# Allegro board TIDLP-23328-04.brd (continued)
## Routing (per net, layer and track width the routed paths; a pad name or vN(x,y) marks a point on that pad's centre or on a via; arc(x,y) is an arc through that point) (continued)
TIVA_EXP_I2C_SCL: length 24.6
  TOP w0.099: J5.37 38,42 v1(37.68,41.67) ; v2(42.89,27.76) 43.42,27.76 44.83,29.17 46.22,29.17 R25.1
  LY4-SIG w0.102: v2(42.89,27.76) 42.57,27.76 42.18,28.16 42.18,28.52 43.13,29.48 43.13,30 42.81,30.32 42.81,31.16 42.18,31.79 42.18,33.87 40.91,35.14 40.52,35.14 39.45,36.21 39.45,38.89 38.22,40.12 38.22,40.65 37.68,41.2 v1(37.68,41.67)
  BOTTOM w0.099: U1.D2 v2(42.89,27.76)
TIVA_EXP_I2C_SDA: length 24.4
  TOP w0.099: v2(44.73,28.35) 44.82,28.26 45.88,28.26 R26.1 ; v1(38.65,42.18) 38.4,42.43 J5.35
  LY3-SIG w0.102: v2(44.73,28.35) 44.73,29.08 45.16,29.51 45.16,33.73 44.45,34.44 44.45,35.14 44.94,35.63 44.94,36.89 44.26,37.57 43.33,37.57 41.61,39.29 38.72,39.29 38.11,39.9 38.11,41.64 v1(38.65,42.18)
  BOTTOM w0.099: U1.D1 v2(44.73,28.35)
TIVA_FLASH_CLK: length 38.8
  TOP w0.099: v1(40.64,38.04) 40.4,38.28 J5.26
  LY4-SIG w0.102: v1(27.05,35.28) 27.05,30.66 26.74,30.34 26.74,28.13 29.72,25.15 29.72,22.61 30.23,22.1 34.03,22.1 34.27,21.86 37.05,21.86 v2(37.14,21.77)
  LY7-SIG w0.102: v1(27.05,35.28) 27.82,36.05 29.07,36.05 31.09,38.07 39.22,38.07 39.65,37.64 40.24,37.64 v1(40.64,38.04)
  BOTTOM w0.099: U1.U14 v2(37.14,21.77)
TIVA_FLASH_CSZ: length 60.9
  TOP w0.099: J5.24 40.8,38.45 41.28,37.97 41.28,37.6 R17.1 42.17,37.35 v1(42.3,37.22)
  LY7-SIG w0.102: v2(38.38,18.99) 38.38,17.92 38.32,17.87 38.32,17.55 38.38,17.5 38.38,14.81 39.2,13.99 39.91,13.99 40.6,13.31 50.94,13.31 54.71,17.07 54.71,18.46 55.44,19.19 55.44,35.11 54.74,35.81 53.98,35.81 52.24,37.56 49.69,37.56 49.15,38.1 48.33,38.1 47.45,37.22 v1(42.3,37.22)
  BOTTOM w0.099: U1.V12 38.92,20.49 38.92,19.53 v2(38.38,18.99)
TIVA_FLASH_DO: length 36.4
  TOP w0.099: v1(28.17,28.8) 28.95,28.8 30.33,27.42 30.33,26.52 30.94,25.91 30.94,25.3 31.58,24.65 33.45,24.65 33.7,24.89 34.29,24.89 34.38,24.98 34.78,24.98 35.08,24.68 v2(36.64,24.68) ; v1(40.29,41.27) 40,41.56 J5.27
  LY8-SIG w0.102: v1(40.29,41.27) 40.13,41.11 40.13,39.31 38.83,38.02 38.02,38.02 37.62,37.61 37.62,36.71 36.62,35.71 30.07,35.71 28.69,34.34 28.69,29.32 v1(28.17,28.8)
  BOTTOM w0.099: v1(40.29,41.27) 40.29,41.26 ; v2(36.64,24.68) 36.78,24.83 37.08,24.83 U1.K15
TIVA_IIC0_SCL: length 58.3
  TOP w0.099: v1(38.66,37.02) 38.7,37.02 38.75,36.97 38.99,36.97 R35.1 39.2,37.52 J5.32
  LY7-SIG w0.102: v1(38.66,37.02) 41.05,37.02 41.91,36.16 46.9,36.16 48.64,34.42 52.7,34.42 54.29,32.83 54.29,30.5 54.58,30.21 54.58,18.98 54.31,18.71 54.31,17.33 50.73,13.74 41.21,13.74 40.51,14.44 40.51,15.24 39.37,16.38 39.37,18.76 v2(39.14,18.99)
  BOTTOM w0.099: v2(39.14,18.99) U1.V11
TIVA_IIC0_SDA: length 37.7
  TOP w0.099: v2(36.85,24.18) 36.71,24.18 36.34,23.8 35.15,23.8 34.79,23.44 34.25,23.44 34.02,23.2 33.33,23.2 32.89,23.64 30.28,23.64 29.17,24.74 29.17,26.81 28.46,27.52 v1(28.46,27.52) ; J5.30 39.6,38.01 39.88,37.73 40.01,37.73 R36.1 39.81,36.77 39.09,36.77 38.95,36.64 38.18,36.64 38.18,36.63 37.86,36.63 37.86,36.64 36.71,36.64 v1(36.59,36.76)
  LY8-SIG w0.102: v1(36.59,36.76) 29.54,36.76 26.07,33.3 26.07,29.34 27.89,27.52 v1(28.46,27.52)
  BOTTOM w0.099: v2(36.85,24.18) 36.85,23.98 U1.M16
TIVA_RESETZ: length 26.1
  TOP w0.099: U13.6 27.57,15.07 R45.2 27.51,15.86 v1(27.44,15.93)
  LY7-SIG w0.102: v2(33.82,22.56) 31.87,22.56 27.44,18.13 v1(27.44,15.93) 27.44,12.7 24.86,10.11 24.49,10.11 v1(23.14,8.76)
  BOTTOM w0.099: v2(33.82,22.56) 34.81,22.56 34.88,22.49 35.36,22.49 U1.P18 ; J4.10 v1(23.14,8.76)
TIVA_TCK: length 37.7
  TOP w0.099: v2(37.14,30.54) 36.79,30.19 34.98,30.19 34.67,29.88 33.66,29.88 33.35,30.19 v1(28.15,30.19)
  BOTTOM w0.099: U1.B15 37.14,28.87 37.16,28.89 37.16,30.52 v2(37.14,30.54) ; J4.4 26.95,8.91 26.73,9.12 26.73,10.65 25.91,11.47 25.91,14.82 24.34,16.39 24.34,25.61 25.06,26.33 25.06,27.91 27.04,29.89 27.85,29.89 v1(28.15,30.19)
TIVA_TDI: length 43.2
  TOP w0.099: v1(26.59,31.04) 27.45,31.9 32.85,31.9 34.27,30.48 34.7,30.48 35.13,30.91 37.35,30.91 37.5,30.76 37.5,29.63 38.5,28.63 38.5,28.1 v2(37.64,27.24)
  BOTTOM w0.099: U1.D14 37.64,27.24 v2(37.64,27.24) ; v1(26.59,31.04) 26.59,30.37 25.43,29.21 24.76,29.21 23.88,28.33 23.88,26.42 23.42,25.96 23.42,14.68 24.09,14.01 24.09,10.4 24.41,10.09 J4.8
TIVA_TDO: length 38.7
  TOP w0.099: v1(27.56,30.48) 27.56,30.13 27.87,29.81 32.24,29.81 32.91,29.15 33.33,29.15 33.8,29.61 34.63,29.61 34.97,29.27 37.11,29.27 v2(38.12,28.26)
  BOTTOM w0.099: v1(27.56,30.48) 27.15,30.48 27.05,30.38 27.05,30.35 24.48,27.78 24.48,26.38 23.84,25.74 23.84,15.03 24.67,14.2 24.67,12.16 25.08,11.75 25.08,9.61 25.68,9 J4.6 ; U1.C14 v2(38.12,28.26)
TIVA_TMS: length 36
  TOP w0.099: v1(28.17,29.43) 32.18,29.43 32.84,28.77 33.14,28.77 33.78,28.13 34.14,28.13 34.62,28.61 36.75,28.61 37.14,28.22 v2(37.14,27.83)
  BOTTOM w0.099: J4.2 28.22,7.86 27.7,8.38 27.7,8.76 27.08,9.37 27.08,14.5 24.92,16.67 24.92,19.96 26.09,21.14 26.09,23.55 26.8,24.26 26.8,28.06 v1(28.17,29.43) ; U1.C15 v2(37.14,27.83)
TIVA_TRIG_IN_0: length 21.6
  TOP w0.099: v1(38.62,40.39) 38.55,40.39 38,39.85 J5.38
  LY3-SIG w0.102: v1(38.62,40.39) 38.62,40 38.99,39.63 41.65,39.63 43.43,37.85 44.76,37.85 45.32,37.28 45.32,34.4 45.56,34.16 45.56,29.31 45.12,28.87 45.12,28.21 44.66,27.75 v2(44.66,26.53)
  BOTTOM w0.099: U1.G1 44.39,26.26 v2(44.66,26.53)
TIVA_TRIG_IN_1: length 22.7
  TOP w0.099: v1(36.93,37.53) 37.6,38.2 J5.40
  LY3-SIG w0.102: v2(45.25,26.53) 45.25,26.36 44.92,26.03 44.53,26.03 44.27,26.29 44.27,28.63 43.56,29.34 43.56,33.86 42.92,34.5 42.92,35.98 41.26,37.64 39.71,37.64 39.26,38.09 37.5,38.09 v1(36.93,37.53)
  BOTTOM w0.099: v2(45.25,26.53) 45.25,26.36 44.88,25.99 43.92,25.99 U1.G2
TIVA_TRIG_SEL: length 20.4
  TOP w0.099: v1(37.43,40.39) 37.2,40.16 J5.42
  LY3-SIG w0.102: v2(43.97,30.54) 44.63,30.54 44.85,30.75 44.85,33.47 43.84,34.48 43.84,35.51 44.62,36.3 44.62,36.75 44.15,37.23 43.16,37.23 41.61,38.79 38.22,38.79 37.43,39.58 v1(37.43,40.39)
  BOTTOM w0.099: U1.B2 43.31,29.1 43.31,29.51 43.39,29.58 43.39,29.69 43.46,29.76 43.46,30.16 43.83,30.54 v2(43.97,30.54)
TIVA_VSYNC_MASK: length 15.7
  LY4-SIG w0.102: v1(48.68,36.44) 48.63,36.44 48.37,36.18 48.37,36.18 48.15,35.96 48.15,35.95 48.13,35.94 48.13,34.92 48.64,34.42 48.64,34.04 47.56,32.95 47.56,30.73 47.18,30.35 46.87,30.35 46.23,29.71 46.23,27.18 45.85,26.8 v2(45.85,25.78)
  BOTTOM w0.099: v2(45.85,25.78) 45.72,25.78 45.7,25.76 U1.H2 ; v1(48.68,36.44) 48.79,36.33 U9.5
TSCL: length 17.2
  LY8-SIG w0.102: v1(38.02,37.01) 38.02,37.01 38.02,36.04 38.56,35.49 39.79,35.49 41.5,33.78 43.8,33.78 44.97,32.61 44.97,29.26 44.35,28.63 43.5,28.63 v2(43.13,28.26)
  BOTTOM w0.099: U1.C2 v2(43.13,28.26) ; v1(38.02,37.01) 38.02,37.01 37.95,37.08 J2.13
TSDA: length 21.1
  BOTTOM w0.099: U1.C1 44.14,28.32 45.38,29.56 45.38,31.58 42.88,34.09 42.88,37.92 41.81,38.99 41.31,38.99 39.49,40.81 36.48,40.81 36.23,40.56 36.23,40.06 35.95,39.79 J2.11
U4CTS: length 24.9
  LY4-SIG w0.102: v1(38,7.57) 38,8.19 38.55,8.74 38.99,8.74 39.23,8.5 40.85,8.5 42.37,10.02 42.37,11.14 43.48,12.25 43.48,13.51 42.97,14.02 42.97,16.2 43.59,16.83 43.59,18.32 44.12,18.85 44.12,19.19 43.74,19.58 43.74,20.93 43.76,20.95 43.76,20.96 43.92,21.11 43.92,23.66 43.61,23.96 43.61,24.86 v2(43.19,25.28)
  BOTTOM w0.099: v2(43.19,25.28) 43.19,25.21 U1.K2 ; J3.8 v1(38,7.57)
U4RTS: length 24.6
  LY4-SIG w0.102: v2(45.59,24.3) 45.31,24.3 44.89,23.88 44.36,23.88 44.26,23.78 44.26,21.4 44.58,21.08 44.58,18.8 43.94,18.16 43.94,17.57 44.3,17.21 44.3,12.37 42.82,10.89 42.82,9.93 40.83,7.95 39.04,7.95 v1(38.71,8.28)
  BOTTOM w0.099: J3.7 v1(38.71,8.28) ; v2(45.59,24.3) 45.4,24.3 44.94,24.76 44.63,24.76 44.63,24.77 U1.K1
USB_DAT_N: length 26.3
  TOP w0.102: U3.2 17.86,33.47 v1(17.23,34.09)
  LY7-SIG w0.109: v1(17.23,34.09) 17.23,34.36 16.81,34.77 16.81,35.55 17.39,36.12 21.51,36.12 23.39,34.24 26.49,34.24 30.59,30.14 31.7,30.14 32.79,29.05 33.44,29.05 33.55,29.16 33.9,29.16 v2(33.94,29.13)
  BOTTOM w0.102: v2(33.94,29.13) 33.94,29.09 34.55,28.49 35.36,28.49 U1.B18 ; v1(17.23,34.09) 16.42,34.91 J1.2
USB_DAT_P: length 25.5
  TOP w0.102: v1(17.68,34.54) 17.68,34.22 U3.1
  LY7-SIG w0.109: v2(33.95,28.54) 33.92,28.58 33.58,28.58 33.39,28.77 32.68,28.77 31.59,29.86 30.48,29.86 26.38,33.96 23.28,33.96 21.4,35.84 17.5,35.84 17.09,35.43 17.09,34.89 17.44,34.54 v1(17.68,34.54)
  BOTTOM w0.102: J1.3 16.88,35.34 v1(17.68,34.54) ; v2(33.95,28.54) 33.95,28.51 34.28,28.18 35.49,28.18 35.57,28.26 U1.C18
USB_ID: length 29.7
  TOP w0.099: U3.3 17.65,32.83 v1(17.65,31.62)
  LY7-SIG w0.102: v2(36.38,29.78) 35.88,29.78 34.29,28.19 33.81,28.19 33.46,27.83 33.46,27.57 33.25,27.36 32.72,27.36 32.28,27.79 32.28,28.35 31.46,29.18 29.96,29.18 28.56,30.57 28.22,30.57 27.32,31.48 19.94,31.48 19.52,31.05 18.22,31.05 v1(17.65,31.62)
  BOTTOM w0.099: U1.A16 36.38,29.53 v2(36.38,29.78) ; J1.4 18.54,34.64 18.54,34.02 17.4,32.88 17.4,31.88 v1(17.65,31.62)
USB_VBUS: length 8.2
  TOP w0.254: v1(19.43,32.26) 19.17,32.52 19.17,32.54 18.92,32.8 U3.6
  BOTTOM w0.127: U1.B16 36.93,29.06 36.93,29.39 36.93,29.99 v2(36.38,30.54)
  BOTTOM w0.254: R59.1 20.32,31.37 v1(19.43,32.26) 19.43,32.34 C14.1
  BOTTOM w0.381: J1.1 16.34,34.08 16.34,33.82 v1(16.76,33.4) v1(16.76,32.64)
  vias: v1(16.13,32.64) v1(16.13,31.88) v1(16.76,31.88) v1(24.89,25.4) v1(25.53,26.04) v1(25.53,25.4) v1(25.53,24.77) v1(26.16,25.78) v1(26.16,25.15)
VSYNC_WE: length 20.6
  TOP w0.099: R39.1 v1(48.53,35.8)
  LY4-SIG w0.102: v1(48.53,35.8) 48.78,35.8 49.28,35.31 49.28,33.91 48.9,33.53 48.9,32.51 47.88,31.5 47.88,29.59 46.54,28.25 46.54,25.84 46.13,25.43 45.66,25.43 45.48,25.6 44.62,25.6 44.45,25.76 42.81,25.76 42.08,25.03 42.08,24.02 v2(42.22,23.87)
  BOTTOM w0.099: U9.4 49.59,35.8 v1(48.53,35.8) ; U1.N4 42.23,23.68 42.23,23.87 v2(42.22,23.87)
VSYNC_WE_B: length 19.1
  TOP w0.099: R33.2 47.93,37.08 v1(48.64,37.08) 48.88,36.84 R39.2 ; v1(36.43,41.54) 36.43,41.44 36.4,41.42 J5.46
  LY3-SIG w0.102: v1(36.43,41.54) 36.46,41.54 36.62,41.7 36.89,41.7 37.24,42.06 37.71,42.06 38.22,42.56 39.22,42.56 39.89,41.89 41.83,41.89 43.43,40.29 43.43,40.08 46.43,37.08 v1(48.64,37.08)
XOSC0: length 11.6
  BOTTOM w0.099: U1.T18 35.31,22.1 33.53,22.1 33.27,22.35 33.27,24.3 C29.2 32.21,25.36 32.21,26.36 32.01,26.57 30.73,26.57 30.32,26.16 29.21,26.16 28.87,25.82 Y1.1
XOSC1: length 6.3
  BOTTOM w0.099: Y1.2 31.41,22.95 31.86,22.49 C30.2 33.39,21.77 U1.T19
N42370442: length 2.5
  TOP w0.099: U10.22 25.43,27.7 R48.2
N42370449: length 1.8
  TOP w0.099: R49.2 19.17,27.2 U10.10
N42370456: length 2.1
  TOP w0.099: U10.20 26.17,26.7 C77.2
N42417768: length 7.5
  TOP w0.099: C63.2 27.97,26.83 27.97,24.71 27.98,24.7 27.98,24.07 27.97,24.06 27.97,23.78 27.69,23.5 25.78,23.5 25.42,23.86 L2.1
N42417797: length 2.2
  TOP w0.099: U10.21 25.96,27.2 C63.1
N42420916: length 8.7
  TOP w0.099: v1(25.53,29.84) 25.53,28.83 24.9,28.2 U10.23
  BOTTOM w0.099: v1(25.53,29.84) 25.91,30.23 25.91,30.99 25.53,31.37 R59.2 R60.1
N42420946: length 59.5
  TOP w0.099: U10.7 19.81,28.7 19.43,29.08 19.43,29.72 v1(19.18,29.97) ; D4.2 44.48,10.42 v1(43.97,9.91)
  LY3-SIG w0.102: v1(19.18,29.97) 18.85,30.3 17.58,30.3 15.79,28.51 15.79,27.01 16.84,25.96 17.59,25.96 18.8,24.75 18.8,23.75 18.03,22.99 18.03,20.83 20.23,18.63 20.23,18.36 23.14,15.45 24.03,15.45 24.2,15.62 24.67,15.62 24.84,15.45 25.19,15.45 28.25,12.39 28.25,11.28 28.85,10.68 30.75,10.68 33.57,7.86 33.57,6.63 37.02,3.18 41.69,3.18 46.37,7.69 46.37,8.35 44.81,9.91 v1(43.97,9.91)
N42420948: length 0.9
  TOP w0.099: R42.1 45.85,9.06 D4.1
N42627428: length 7.7
  TOP w0.254: U13.3 34.44,15.07 34.64,14.87 34.64,14.56 ; U13.2 34.5,14.42 34.64,14.56 ; 34.64,14.56 36.25,12.95 v1(36.25,12.19)
  BOTTOM w0.254: v1(36.25,12.19) 36.25,11.21 R43.2 R46.2
N42627469: length 24.1
  TOP w0.099: SW3.1 v1(50.45,15.11) ; U13.7 v1(30.75,14.42)
  BOTTOM w0.099: v1(50.45,15.11) 43.34,15.11 42.09,16.36 35.93,16.36 33.99,14.42 v1(30.75,14.42)
N43128043: length 3.2
  TOP w0.099: U17.4 44.23,33.63 45.72,32.13 U18.1
N43128052: length 3.4
  TOP w0.099: U16.4 41.02,33.63 41.45,33.19 41.45,32.88 42.17,32.17 U17.1
N43142748: length 3.9
  TOP w0.099: U15.4 36.89,33.63 37.82,32.7 38.78,32.7 39.26,32.22 U16.2
N43167198: length 1.7
  TOP w0.099: v1(48.76,35.13) 49,34.89 R34.1
  BOTTOM w0.099: v1(48.76,35.13) 48.96,35.33 U9.3
N43167201: length 2.5
  TOP w0.099: R33.1 48.72,37.67 v1(48.77,37.72)
  BOTTOM w0.099: v1(48.77,37.72) 49.28,37.72 49.62,37.38 U9.6
N43219788: length 4.7
  TOP w0.254: v2(37.47,25.25) 37.39,25.33 36.94,25.33 C51.1 ; C52.1 39.98,27.73 v2(40.16,27.73) ; C54.2 v1(32.84,26.74)
  BOTTOM w0.203: U1.E10 39.67,27.26 40.14,27.73 v2(40.16,27.73) ; U1.H16 37.07,25.33 37.39,25.33 v2(37.47,25.25)
  BOTTOM w0.254: C53.1 v1(40.69,33.22)
N43219848: length 9.3
  TOP w0.099: C32.1 R32.1 36.58,18.19 34.57,20.2 v2(34.57,23.05)
  BOTTOM w0.099: v2(34.57,23.05) 34.81,22.81 35.09,22.81 U1.P19
N43219986: length 1
  TOP w0.099: R24.1 D3.1
N43219998: length 1
  TOP w0.099: R23.1 D2.1
N43220038: length 1
  TOP w0.099: R22.1 D1.1
N43220044: length 17
  TOP w0.099: D3.2 v1(39.75,5.71)
  LY3-SIG w0.102: v2(40.66,18.99) 40.66,14.2 41.92,12.95 41.92,9.28 40.13,7.49 40.13,6.1 v1(39.75,5.71)
  BOTTOM w0.099: U1.W7 41.02,20.14 41.02,19.34 v2(40.66,18.99)
N43220071: length 19.4
  TOP w0.099: D2.2 v1(41.4,7.37)
  LY3-SIG w0.102: v1(41.4,7.37) 42.42,8.38 42.42,10.54 43.43,11.56 43.43,13.67 42.99,14.11 42.99,16.71 44.43,18.15 45.57,18.15 46.25,18.83 v2(46.25,19.75)
  BOTTOM w0.099: U1.V2 43.92,21.04 44.25,21.04 44.26,21.04 44.46,21.04 45.74,19.75 v2(46.25,19.75)
N43220075: length 32.8
  TOP w0.099: D1.2 v1(43.21,9.17)
  LY3-SIG w0.102: v1(43.21,9.17) 43.21,7.9 40.39,5.08 39.5,5.08 37.97,6.6 37.97,6.86 37.34,7.49 37.34,16.64 33.27,20.7 33.27,25.44 v2(33.86,26.03)
  BOTTOM w0.099: U1.H18 35.36,25.49 34.4,25.49 v2(33.86,26.03)
N43273215: length 9.1
  BOTTOM w0.508: F1.1 10.98,33.31 J1.9 J1.8 J1.7 J1.6
N43274901: length 33.8
  TOP w0.099: v2(35.71,30.54) 35.05,30.54 34.78,30.28 33.82,30.28 33.19,30.91 27.29,30.91 27.08,30.71 27.08,30.09 27.77,29.4 27.77,28.96 27.79,28.94 27.79,28.3 27.72,28.23 27.72,27.59 28.58,26.73 28.58,23.87 29.08,23.37 29.08,18.29 27.18,16.38 26.16,16.38 25.91,16.13 25.91,14.61 25.4,14.1 24.88,14.1 R21.2 22.98,12.2 U7.B1
  BOTTOM w0.099: v2(35.71,30.54) 35.71,29.69 U1.A17
N43275105: length 1.3
  BOTTOM w0.099: R11.1 8.52,13.61 U4.8
N43275134: length 1.5
  TOP w0.099: R6.1 4.78,9.17 P1.8
N43328704: length 2.3
  BOTTOM w0.099: U19.5 15.1,22.75 14.99,22.86 14.99,23 15.08,23.1 U19.6 14.9,23.37 14.48,23.37 R56.1
N43328728: length 1.1
  BOTTOM w0.099: R57.2 15.74,22.01 U19.3
N43392226: length 4.1
  BOTTOM w0.099: U1.D19 35.03,27.88 34.01,27.88 33.59,28.3 33.59,28.83 33.52,28.9 33.52,29.34 33.72,29.53 33.72,30.28 R30.1
N43392629: length 2.8
  BOTTOM w0.099: R30.2 32.89,30.87 C88.2 31.59,30.87 Y2.3

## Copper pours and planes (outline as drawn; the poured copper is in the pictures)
GND on TOP (solid shape): 23.48,26.18 20.94,26.18 20.94,28.72 23.48,28.72
GND on BOTTOM (solid shape): 8.85,15.54 6.7,15.54 6.7,18.19 8.85,18.19
GND on BOTTOM (solid shape): 51.77,36.9 52.46,36.9 52.46,34.75 51.77,34.75 51.77,33.62 51.01,33.62 51.01,34.75 50.31,34.75 50.31,36.9 51.01,36.9 51.01,38.04 51.77,38.04
GND on TOP: 21.7,20.93 21.7,19.74 21.84,19.6 22.36,19.6 22.52,19.44 22.75,19.44 22.88,19.57 22.88,20.12 23.15,20.38 24.37,20.38 24.74,20.02 26.41,20.02 26.48,19.95 26.66,19.95 26.8,19.81 28.32,19.81 28.45,19.94 28.45,20.95 28.19,21.21 26.94,21.21 26.8,21.06 21.84,21.06
GND on TOP: 17.91,22.23 17.91,24.77 18.16,25.02 18.54,25.02 19.43,24.13 19.43,22.35 19.05,21.97 18.16,21.97
GND on TOP: 25.81,11.94 25.81,13.46 26.19,13.84 26.57,13.84 26.7,13.72 26.7,9.91 26.57,9.78 25.68,9.78 25.43,10.03 25.43,11.56
GND on TOP: 21.84,26.42 21.84,23.11 21.97,22.99 22.48,22.99 22.99,23.5 22.99,23.75 22.48,24.26 22.48,26.16 22.73,26.42
GND on BOTTOM: 0.64,10.38 0.64,0.56 21.93,0.56 21.93,20 1.43,20 1.43,11.17 ; 6 cut-outs
GND on LY2-GND: 38.95,0.76 0.76,0.76 0.76,10.5 1.43,11.17 1.43,21.77 0.76,22.43 0.76,24.67 21.21,44.42 61.04,44.42 61.04,32.49 61.04,22.1 ; 12 cut-outs
GND on LY8-SIG: 0.64,0.38 0.64,9.78 21.84,9.78 21.84,0.38
GND on LY9-GND: 38.95,0.76 0.76,0.76 0.76,10.5 1.43,11.17 1.43,21.77 0.76,22.43 0.76,24.67 21.21,44.42 61.04,44.42 61.04,32.49 61.04,22.1 ; 13 cut-outs
LI-ION_BATTERY on TOP: 16.24,26.16 18.49,26.16 19.11,26.78 20.26,26.78 20.38,26.66 20.38,26.22 20.26,26.1 19.64,26.1 19.07,25.53 18.49,25.53 16.89,23.92 16.05,23.92 15.35,24.62 15.35,25.28
LI-ION_BATTERY on BOTTOM: 9,24.24 9.99,24.24 11.25,22.98 11.86,22.98 12.41,22.43 12.41,21 11.99,20.59 10,20.59 8.57,22.02 8.57,23.82
LI-ION_BATTERY on LY3-SIG: 9.75,24.02 9.75,21.21 10.5,20.46 14.83,20.46 17.69,23.32 17.69,25.2 17.34,25.55 11.27,25.55
P1P8V on LY4-SIG: 22.1,8.13 22.1,10.92 22.61,11.43 27.18,11.43 27.94,10.67 30.1,10.67 30.99,11.56 34.67,11.56 35.94,10.29 35.94,8.13 37.47,6.6 40.51,6.6 56.13,22.23 56.13,31.88 48.9,39.12 43.56,39.12 42.67,40.01 42.67,41.78 42.29,42.16 42.29,42.93 42.55,43.18 50.04,43.18 59.69,33.53 59.69,21.08 42.42,3.81 35.43,3.81 33.15,6.1 24.13,6.1
P1P8V_BT on LY8-SIG: 6.86,17.65 6.86,13.21 7.49,12.57 9.65,12.57 12.95,9.27 14.35,9.27 15.49,10.41 21.72,10.41 22.35,11.05 22.35,17.02 20.19,19.18 8.38,19.18
P3P3V on TOP: 22.48,18.36 22.48,18.15 22.79,17.85 23.8,17.85 24.78,16.87 25.02,16.87 25.12,16.76 27.05,16.76 27.43,17.14 27.43,18.54 27.05,18.92 26.79,18.92 26.73,18.98 24.98,18.98 24.23,18.23 23.48,18.23 23.27,18.44 22.57,18.44
P3P3V on LY6-PWR: 38.95,0.76 0.76,0.76 0.76,10.5 1.43,11.17 1.43,21.77 0.76,22.43 0.76,24.67 21.21,44.42 61.04,44.42 61.04,32.49 61.04,22.1 ; 12 cut-outs
P5P0V on TOP: 32.41,11.18 32.41,10.54 32.16,10.29 31.78,10.29 31.65,10.41 31.65,14 31.75,14.1 32.26,14.1 32.51,13.84 32.51,11.28
P5P0V on LY3-SIG: 25.65,24.26 25.65,22.61 33.78,14.48 33.78,12.95 33.02,12.19 32.38,12.19 31.88,12.7 31.88,13.46 29.59,15.75 27.18,15.75 22.73,20.19 22.73,23.5 19.81,26.42 19.81,36.83 21.34,38.35 25.78,38.35 26.54,37.59 26.54,36.83 25.65,35.94 24,35.94 22.99,34.92 22.99,26.92 ; 2 cut-outs
SYS_PWR on TOP: 19.68,21.21 19.44,20.97 19.44,18.28 19.81,17.91 20.6,17.91 20.98,18.29 20.98,20.83 21.74,21.59 25.02,21.59 25.15,21.72 25.15,21.97 24.89,22.23 22.61,22.23 22.1,22.73 21.84,22.73 21.59,22.99 21.59,25.4 21.46,25.53 20.45,25.53 20.07,25.15 20.07,22.73 19.68,22.35
SYS_PWR on TOP: 44.83,44.17 45.91,44.17 46.4,43.68 46.4,39.25 45.96,38.81 44.91,38.81 44.76,38.96 44.76,39.66 45.6,40.49 45.6,42.56 44.74,43.42 44.74,44.08
SYS_PWR on TOP: 27.46,13.84 29.49,13.84 29.62,13.72 29.62,13.46 29.36,13.21 28.73,13.21 28.35,12.83 28.35,10.79 28.68,10.47 30.45,10.47 30.89,10.03 30.89,9.78 30.38,9.27 27.84,9.27 27.46,9.65
SYS_PWR on BOTTOM: 29.36,8.64 31.52,8.64 31.65,8.51 31.9,8.51 32.41,8 33.43,8 33.55,8.13 33.55,9.14 34.06,9.65 34.06,9.78 33.81,10.03 27.97,10.03 27.71,9.78 27.71,9.4 27.97,9.14 28.85,9.14 ; 1 cut-out
SYS_PWR on LY5-PWR: 38.95,0.76 0.76,0.76 0.76,10.5 1.43,11.17 1.43,21.77 0.76,22.43 0.76,24.67 21.21,44.42 61.04,44.42 61.04,32.49 61.04,22.1 ; 13 cut-outs
USB_VBUS on TOP: 24.13,26.29 24.13,25.78 24.64,25.27 24.64,25.15 25.27,24.51 25.78,24.51 26.16,24.13 26.67,24.13 26.8,24.26 26.8,25.65 26.16,26.29
USB_VBUS on BOTTOM: 15.88,34.67 16,34.67 17.14,33.53 17.14,31.75 16.89,31.5 16,31.5 15.75,31.75 15.75,33.02 16.13,33.4 16.13,34.04 15.75,34.42 15.75,34.54
USB_VBUS on LY8-SIG: 15.88,33.15 15.88,28.96 20.32,24.51 28.83,24.51 31.24,26.92 31.24,30.61 31.75,31.11 34.92,31.11 35.94,30.1 36.58,30.1 36.96,30.48 36.96,31.5 36.07,32.38 31.24,32.38 29.47,30.61 29.47,28.09 28.57,27.19 27.55,27.19 25.02,29.72 22.99,29.72 18.54,34.16 16.89,34.16
N42417768 on TOP: 22.89,25.65 23.88,25.65 24.89,24.64 24.89,23.88 24.77,23.75 24,23.75 23.37,24.38 23.11,24.38 22.87,24.63 22.87,24.88 22.89,24.89
N42627229 on TOP: 21.68,18.41 21.77,18.41 21.83,18.35 21.83,17.43 21.64,17.25 21.64,15.78 21.17,15.31 20.91,15.31 20.68,15.54 20.68,16.92 21.6,17.85 21.6,18.33
N42627251 on TOP: 22.05,18.37 22.05,17.48 22.34,17.19 22.34,15.71 22.62,15.42 23.06,15.42 23.19,15.55 23.19,17.08 22.26,18.01 22.26,18.37 22.22,18.41 22.08,18.41
N42627452 on TOP: 33.3,13.84 34.32,13.84 34.44,13.72 34.44,12.32 34.32,12.19 33.3,12.19 33.17,12.32 33.17,13.72
N42627511 on TOP: 22.48,18.83 22.48,18.74 22.55,18.68 23.89,18.68 23.99,18.78 23.99,19.79 23.87,19.92 23.65,19.92 23.4,19.67 23.4,19.31 23.06,18.97 22.63,18.97
N43219788 on LY3-SIG: 32.56,27.16 32.56,26.65 32.75,26.45 34.06,26.45 35.13,25.38 35.13,24.35 35.82,23.65 37.6,23.65 38.12,24.18 38.12,25.45 37.77,25.8 37.02,25.8 36.54,25.31 36.48,25.31 34.15,27.65 33.04,27.65
N43219788 on LY4-SIG: 40.04,33.51 40.78,33.51 40.97,33.32 40.97,28.07 40.34,27.44 40.1,27.44 39.9,27.64 39.9,33.38
N43219788 on LY7-SIG: 37.23,25.43 37.23,25.04 37.5,24.77 38.82,24.77 39.79,25.74 39.79,26.93 40.39,27.53 40.39,28.07 40.18,28.29 39.55,28.29 39.19,27.93 39.19,26.23 38.69,25.73 37.44,25.73 37.24,25.52 37.24,25.43

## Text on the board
BOTTOM: LAYER 10 - SECONDARY SIDE | 10
Ref Des/Assembly Bottom: ASSEMBLY - SECONDARY SIDE | 2   2
Board Geometry/Soldermask Bottom: SOLDERMASK - SECONDARY SIDE | 12
Ref Des/Silkscreen Bottom: JTAG | Detector | 1 | A | Battery | USB | SILKSCREEN - SECONDARY SIDE | 14
TOP: LAYER 1 - PRIMARY SIDE | 1
Ref Des/Assembly Top: ASSEMBLY - PRIMARY SIDE | 1   2
Board Geometry/Soldermask Top: SOLDERMASK - PRIMARY SIDE | 11
Ref Des/Silkscreen Top: CCA 2514149 | MSN [     ] | PCB 2514148 | ESD 2514147 | Texas Instruments | DLP NIRscan Nano Tiva board | R | TM | ACD# TIDLP-23328-04 | Reset | On/Off | Scan | SILKSCREEN - PRIMARY SIDE | 13
LY2-GND: Layer 2 - GND PLANE | 2
LY3-SIG: Layer 3 - SIGNAL | 3
LY4-SIG: LAYER 4 - SIGNAL | 4
LY5-PWR: Layer 5 - PWR PLANE | 5
LY6-PWR: Layer 6 - PWR PLANE | 6
LY7-SIG: Layer 7 - SIGNAL | 7
LY8-SIG: Layer 8 - SIGNAL | 8
LY9-GND: LAYER 9 - GND PLANE | 9
DIMENSION: SOLDERPASTE - PRIMARY SIDE | FAB DRAWING | 17 | 15 | 4 MIL TRACES ON INTERNAL LAYERS SHALL HAVE A SINGLE ENDED | 3.9 MIL TRACES ON EXTERNAL LAYERS SHALL HAVE A SINGLE ENDED | LAYER 2 - GND PLANE | LAYER 3 - SIGNAL | LAYER 4 - SIGNAL | LAYER 5 - PWR PLANE | LAYER 6 - PWR PLANE | LAYER 7 - SIGNAL | LAYER 8 - SIGNAL | LAYER 9 - GND PLANE | LAYER 10 - SECONDARY SIDE | LAYER STACKUP | LAYER 1 - PRIMARY SIDE | ADJUST DIELECTRIC THICKNESSES TO MEET SPECIFIED IMPEDANCE | SHALL HAVE A DIFFERENTIAL IMPEDANCE OF 90 OHMS +/- 10% | 4.3 MIL TRACES WITH 6.7 MIL SPACING ON INTERNAL LAYERS | 4 MIL TRACES WITH 8 MIL SPACING ON EXTERNAL LAYERS | IMPEDANCE OF 50 OHMS +/- 10% | CONTROLLED IMPEDANCE | MIN. FINAL Cu WEIGHT | 1 oz | 0.5 oz | Primary Side Shown
PLACE_BOUND_TOP: SOLDERPASTE - SECONDARY SIDE | 16
User.18: NIRscan Nano DMD Board | 2514148 | TEXAS INSTRUMENTS | 06 AUG 2015 | TIDLP-23328-04 | 17
User.30: FIGURE | SIZE | 8.0 | 12.0 | 21.654 | 96.0 | 35.0 | DRILL CHART: TOP to BOTTOM | ALL UNITS ARE IN MILS | TOLERANCE | +3.0/-8.0 | +3.0/-12.0 | +2.0/-2.0 | +3.0/-3.0 | PLATED | NON-PLATED | QTY | 681 | 16 | 14 | 3 | 2
